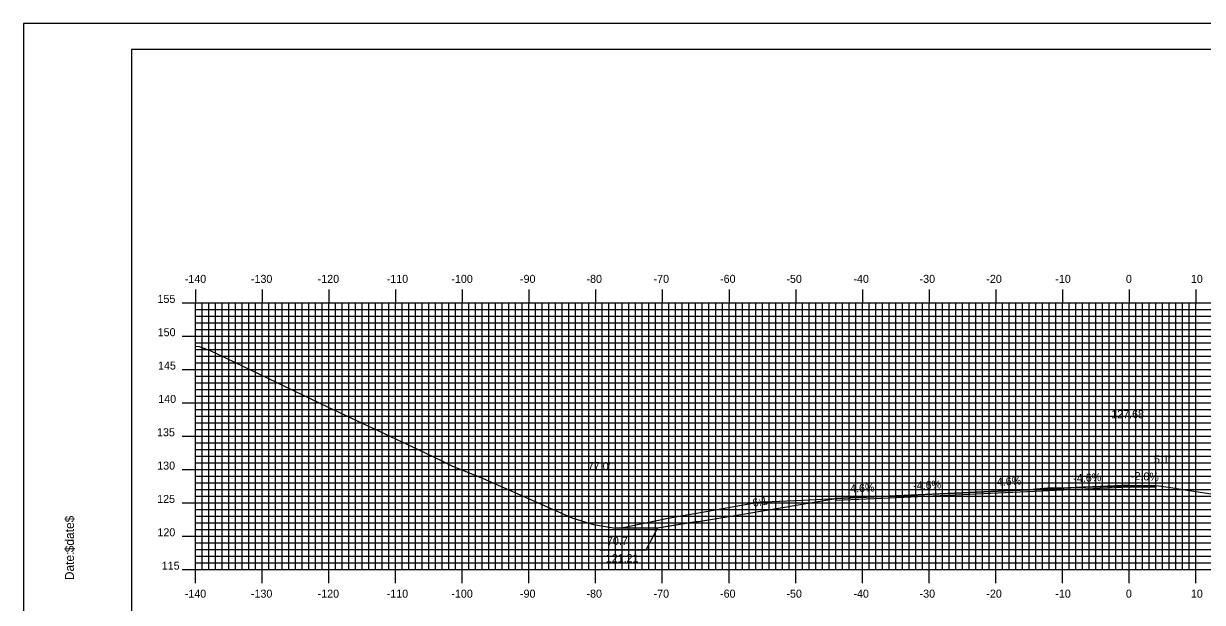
# Model space of a CAD drawing. Extents: x 851926 to 852269, y 366605 to 366825.
# Drawn here: x 851926.2 to 852103, y 366738.1 to 366824.9 of the extents above; entities that cross this region are included whole.
import ezdxf

# ---------------------------------------------------------------- set-up
doc = ezdxf.new("R2010")
doc.units = 0
for name, color, linetype in [('ANNOTATION', 7, 'Continuous'), ('BORDER', 7, 'Continuous'), ('D_Roadway_Centerline', 7, 'Continuous'), ('D_Roadway_Centerline_Text', 7, 'Continuous'), ('D_Roadway_Edge_Shoulder', 7, 'Continuous'), ('D_Roadway_Edge_TW', 7, 'Continuous'), ('D_Roadway_SlopeLines', 7, 'Continuous'), ('D_Text_Standard', 7, 'Continuous'), ('H_V ANNOTATION', 7, 'Continuous'), ('M_Roadway_Centerline', 7, 'Continuous'), ('MAJOR', 7, 'Continuous'), ('MINOR', 7, 'Continuous'), ('PLOT BOUNDARY', 7, 'Continuous'), ('S_Roadway_Centerline', 7, 'Continuous')]:
    doc.layers.add(name, color=color, linetype=linetype)

msp = doc.modelspace()

# ---------------------------------------------------------------- linework, layer by layer
at = {"layer": 'ANNOTATION'}
for points in [[(852027.25, 366750.26), (852021.25, 366749.26), (852014.95, 366749.3)], [(852012.59, 366746.05), (852019.52, 366746.05), (852021.25, 366749.26)]]:
    msp.add_lwpolyline(points, dxfattribs=at)
at = {"layer": 'BORDER'}
msp.add_lwpolyline([(851942.36, 366611.06), (852262.36, 366611.06), (852262.36, 366821.06), (851942.36, 366821.06)], close=True, dxfattribs=at)
at = {"layer": 'D_Roadway_Centerline'}
for p, q in [((852091.96, 366755.74), (852095.96, 366755.66)), ((852091.96, 366755.49), (852095.96, 366755.41))]:
    msp.add_line(p, q, dxfattribs=at)
for points in [[(852025.87, 366750.03), (852033.75, 366751.34), (852047.96, 366753.71), (852047.97, 366753.71), (852052.55, 366753.92), (852055.96, 366754.08), (852055.96, 366754.08), (852062.39, 366754.38), (852067.96, 366754.63), (852067.96, 366754.63), (852079.96, 366755.19), (852079.96, 366755.19), (852091.96, 366755.74), (852091.96, 366755.74), (852095.96, 366755.66)], [(852025.87, 366750.03), (852021.25, 366749.26), (852014.95, 366749.3)]]:
    msp.add_lwpolyline(points, dxfattribs=at)
at = {"layer": 'D_Roadway_Edge_Shoulder'}
for points in [[(852091.96, 366755.74), (852095.96, 366755.66), (852095.96, 366755.41), (852091.96, 366755.49)], [(852055.96, 366754.08), (852047.96, 366753.71), (852047.96, 366753.46), (852055.96, 366753.83)]]:
    msp.add_lwpolyline(points, close=True, dxfattribs=at)
at = {"layer": 'D_Roadway_Edge_TW'}
for points in [[(852079.96, 366755.19), (852067.96, 366754.63), (852067.96, 366754.38), (852079.96, 366754.94)], [(852091.96, 366755.74), (852079.96, 366755.19), (852079.96, 366754.94), (852091.96, 366755.49)], [(852067.96, 366754.63), (852055.96, 366754.08), (852055.96, 366753.83), (852067.96, 366754.38)]]:
    msp.add_lwpolyline(points, close=True, dxfattribs=at)
msp.add_lwpolyline([(852067.96, 366754.38), (852067.96, 366754.63)], dxfattribs=at)
at = {"layer": 'D_Roadway_SlopeLines'}
msp.add_line((852095.96, 366755.66), (852097.11, 366755.51), dxfattribs=at)
at = {"layer": 'MAJOR'}
for p, q in [((851951.96, 366785.06), (851951.96, 366783.06)), ((851961.96, 366785.06), (851961.96, 366783.06)), ((851971.96, 366785.06), (851971.96, 366783.06)), ((851981.96, 366785.06), (851981.96, 366783.06)), ((851991.96, 366785.06), (851991.96, 366783.06)), ((852001.96, 366785.06), (852001.96, 366783.06)), ((852011.96, 366785.06), (852011.96, 366783.06)), ((852021.96, 366785.06), (852021.96, 366783.06)), ((852031.96, 366785.06), (852031.96, 366783.06)), ((852041.96, 366785.06), (852041.96, 366783.06)), ((852051.96, 366785.06), (852051.96, 366783.06)), ((852061.96, 366785.06), (852061.96, 366783.06)), ((852071.96, 366785.06), (852071.96, 366783.06)), ((852081.96, 366785.06), (852081.96, 366783.06)), ((852091.96, 366785.06), (852091.96, 366783.06)), ((852101.96, 366785.06), (852101.96, 366783.06)), ((851949.96, 366783.06), (851951.96, 366783.06)), ((851951.96, 366783.06), (852231.96, 366783.06)), ((851951.96, 366743.06), (851951.96, 366783.06)), ((851951.96, 366743.06), (851951.96, 366783.06)), ((851951.96, 366783.06), (852231.96, 366783.06)), ((851961.96, 366743.06), (851961.96, 366783.06)), ((851971.96, 366743.06), (851971.96, 366783.06)), ((851981.96, 366743.06), (851981.96, 366783.06)), ((851991.96, 366743.06), (851991.96, 366783.06)), ((852001.96, 366743.06), (852001.96, 366783.06)), ((852011.96, 366743.06), (852011.96, 366783.06)), ((852021.96, 366743.06), (852021.96, 366783.06)), ((852031.96, 366743.06), (852031.96, 366783.06)), ((852041.96, 366743.06), (852041.96, 366783.06)), ((852051.96, 366743.06), (852051.96, 366783.06)), ((852061.96, 366743.06), (852061.96, 366783.06)), ((852071.96, 366743.06), (852071.96, 366783.06)), ((852081.96, 366743.06), (852081.96, 366783.06)), ((852091.96, 366743.06), (852091.96, 366783.06)), ((852101.96, 366743.06), (852101.96, 366783.06)), ((851949.96, 366778.06), (851951.96, 366778.06)), ((851951.96, 366778.06), (852231.96, 366778.06)), ((851949.96, 366773.06), (851951.96, 366773.06)), ((851951.96, 366773.06), (852231.96, 366773.06)), ((851949.96, 366768.06), (851951.96, 366768.06)), ((851951.96, 366768.06), (852231.96, 366768.06)), ((851949.96, 366763.06), (851951.96, 366763.06)), ((851951.96, 366763.06), (852231.96, 366763.06)), ((851949.96, 366758.06), (851951.96, 366758.06)), ((851951.96, 366758.06), (852231.96, 366758.06)), ((851949.96, 366753.06), (851951.96, 366753.06)), ((851951.96, 366753.06), (852231.96, 366753.06)), ((851949.96, 366748.06), (851951.96, 366748.06)), ((851951.96, 366748.06), (852231.96, 366748.06)), ((851949.96, 366743.06), (851951.96, 366743.06)), ((851951.96, 366743.06), (852231.96, 366743.06)), ((851951.96, 366743.06), (852231.96, 366743.06)), ((851951.96, 366741.05), (851951.96, 366743.06)), ((851961.96, 366741.05), (851961.96, 366743.06)), ((851971.96, 366741.05), (851971.96, 366743.06)), ((851981.96, 366741.05), (851981.96, 366743.06)), ((851991.96, 366741.05), (851991.96, 366743.06)), ((852001.96, 366741.05), (852001.96, 366743.06)), ((852011.96, 366741.05), (852011.96, 366743.06)), ((852021.96, 366741.05), (852021.96, 366743.06)), ((852031.96, 366741.05), (852031.96, 366743.06)), ((852041.96, 366741.05), (852041.96, 366743.06)), ((852051.96, 366741.05), (852051.96, 366743.06)), ((852061.96, 366741.05), (852061.96, 366743.06)), ((852071.96, 366741.05), (852071.96, 366743.06)), ((852081.96, 366741.05), (852081.96, 366743.06)), ((852091.96, 366741.05), (852091.96, 366743.06)), ((852101.96, 366741.05), (852101.96, 366743.06))]:
    msp.add_line(p, q, dxfattribs=at)
at = {"layer": 'MINOR'}
for p, q in [((851951.96, 366782.06), (852231.96, 366782.06)), ((851951.96, 366782.06), (851953.97, 366782.06)), ((851952.96, 366743.06), (851952.96, 366783.06)), ((851953.96, 366743.06), (851953.96, 366783.06)), ((851954.96, 366743.06), (851954.96, 366783.06)), ((851955.96, 366743.06), (851955.96, 366783.06)), ((851956.96, 366743.06), (851956.96, 366783.06)), ((851957.96, 366743.06), (851957.96, 366783.06)), ((851958.96, 366743.06), (851958.96, 366783.06)), ((851959.96, 366743.06), (851959.96, 366783.06)), ((851960.96, 366743.06), (851960.96, 366783.06)), ((851962.96, 366743.06), (851962.96, 366783.06)), ((851963.96, 366743.06), (851963.96, 366783.06)), ((851964.96, 366743.06), (851964.96, 366783.06)), ((851965.96, 366743.06), (851965.96, 366783.06)), ((851966.96, 366743.06), (851966.96, 366783.06)), ((851967.96, 366743.06), (851967.96, 366783.06)), ((851968.96, 366743.06), (851968.96, 366783.06)), ((851969.96, 366743.06), (851969.96, 366783.06)), ((851970.96, 366743.06), (851970.96, 366783.06)), ((851972.96, 366743.06), (851972.96, 366783.06)), ((851973.96, 366743.06), (851973.96, 366783.06)), ((851974.96, 366743.06), (851974.96, 366783.06)), ((851975.96, 366743.06), (851975.96, 366783.06)), ((851976.96, 366743.06), (851976.96, 366783.06)), ((851977.96, 366743.06), (851977.96, 366783.06)), ((851978.96, 366743.06), (851978.96, 366783.06)), ((851979.96, 366743.06), (851979.96, 366783.06)), ((851980.96, 366743.06), (851980.96, 366783.06)), ((851982.96, 366743.06), (851982.96, 366783.06)), ((851983.96, 366743.06), (851983.96, 366783.06)), ((851984.96, 366743.06), (851984.96, 366783.06)), ((851985.96, 366743.06), (851985.96, 366783.06)), ((851986.96, 366743.06), (851986.96, 366783.06)), ((851987.96, 366743.06), (851987.96, 366783.06)), ((851988.96, 366743.06), (851988.96, 366783.06)), ((851989.96, 366743.06), (851989.96, 366783.06)), ((851990.96, 366743.06), (851990.96, 366783.06)), ((851992.96, 366743.06), (851992.96, 366783.06)), ((851993.96, 366743.06), (851993.96, 366783.06)), ((851994.96, 366743.06), (851994.96, 366783.06)), ((851995.96, 366743.06), (851995.96, 366783.06)), ((851996.96, 366743.06), (851996.96, 366783.06)), ((851997.96, 366743.06), (851997.96, 366783.06)), ((851998.96, 366743.06), (851998.96, 366783.06)), ((851999.96, 366743.06), (851999.96, 366783.06)), ((852000.96, 366743.06), (852000.96, 366783.06)), ((852002.96, 366743.06), (852002.96, 366783.06)), ((852003.96, 366743.06), (852003.96, 366783.06)), ((852004.96, 366743.06), (852004.96, 366783.06)), ((852005.96, 366743.06), (852005.96, 366783.06)), ((852006.96, 366743.06), (852006.96, 366783.06)), ((852007.96, 366743.06), (852007.96, 366783.06)), ((852008.96, 366743.06), (852008.96, 366783.06)), ((852009.96, 366743.06), (852009.96, 366783.06)), ((852010.96, 366743.06), (852010.96, 366783.06)), ((852012.96, 366743.06), (852012.96, 366783.06)), ((852013.96, 366743.06), (852013.96, 366783.06)), ((852014.96, 366743.06), (852014.96, 366783.06)), ((852015.96, 366743.06), (852015.96, 366783.06)), ((852016.96, 366743.06), (852016.96, 366783.06)), ((852017.96, 366743.06), (852017.96, 366783.06)), ((852018.96, 366743.06), (852018.96, 366783.06)), ((852019.96, 366743.06), (852019.96, 366783.06)), ((852020.96, 366743.06), (852020.96, 366783.06)), ((852022.96, 366743.06), (852022.96, 366783.06)), ((852023.96, 366743.06), (852023.96, 366783.06)), ((852024.96, 366743.06), (852024.96, 366783.06)), ((852025.96, 366743.06), (852025.96, 366783.06)), ((852026.96, 366743.06), (852026.96, 366783.06)), ((852027.96, 366743.06), (852027.96, 366783.06)), ((852028.96, 366743.06), (852028.96, 366783.06)), ((852029.96, 366743.06), (852029.96, 366783.06)), ((852030.96, 366743.06), (852030.96, 366783.06)), ((852032.96, 366743.06), (852032.96, 366783.06)), ((852033.96, 366743.06), (852033.96, 366783.06)), ((852034.96, 366743.06), (852034.96, 366783.06)), ((852035.96, 366743.06), (852035.96, 366783.06)), ((852036.96, 366743.06), (852036.96, 366783.06)), ((852037.96, 366743.06), (852037.96, 366783.06)), ((852038.96, 366743.06), (852038.96, 366783.06)), ((852039.96, 366743.06), (852039.96, 366783.06)), ((852040.96, 366743.06), (852040.96, 366783.06)), ((852042.96, 366743.06), (852042.96, 366783.06)), ((852043.96, 366743.06), (852043.96, 366783.06)), ((852044.96, 366743.06), (852044.96, 366783.06)), ((852045.96, 366743.06), (852045.96, 366783.06)), ((852046.96, 366743.06), (852046.96, 366783.06)), ((852047.96, 366743.06), (852047.96, 366783.06)), ((852048.96, 366743.06), (852048.96, 366783.06)), ((852049.96, 366743.06), (852049.96, 366783.06)), ((852050.96, 366743.06), (852050.96, 366783.06)), ((852052.96, 366743.06), (852052.96, 366783.06)), ((852053.96, 366743.06), (852053.96, 366783.06)), ((852054.96, 366743.06), (852054.96, 366783.06)), ((852055.96, 366743.06), (852055.96, 366783.06)), ((852056.96, 366743.06), (852056.96, 366783.06)), ((852057.96, 366743.06), (852057.96, 366783.06)), ((852058.96, 366743.06), (852058.96, 366783.06)), ((852059.96, 366743.06), (852059.96, 366783.06)), ((852060.96, 366743.06), (852060.96, 366783.06)), ((852062.96, 366743.06), (852062.96, 366783.06)), ((852063.96, 366743.06), (852063.96, 366783.06)), ((852064.96, 366743.06), (852064.96, 366783.06)), ((852065.96, 366743.06), (852065.96, 366783.06)), ((852066.96, 366743.06), (852066.96, 366783.06)), ((852067.96, 366743.06), (852067.96, 366783.06)), ((852068.96, 366743.06), (852068.96, 366783.06)), ((852069.96, 366743.06), (852069.96, 366783.06)), ((852070.96, 366743.06), (852070.96, 366783.06)), ((852072.96, 366743.06), (852072.96, 366783.06)), ((852073.96, 366743.06), (852073.96, 366783.06)), ((852074.96, 366743.06), (852074.96, 366783.06)), ((852075.96, 366743.06), (852075.96, 366783.06)), ((852076.96, 366743.06), (852076.96, 366783.06)), ((852077.96, 366743.06), (852077.96, 366783.06)), ((852078.96, 366743.06), (852078.96, 366783.06)), ((852079.96, 366743.06), (852079.96, 366783.06)), ((852080.96, 366743.06), (852080.96, 366783.06)), ((852082.96, 366743.06), (852082.96, 366783.06)), ((852083.96, 366743.06), (852083.96, 366783.06)), ((852084.96, 366743.06), (852084.96, 366783.06)), ((852085.96, 366743.06), (852085.96, 366783.06)), ((852086.96, 366743.06), (852086.96, 366783.06)), ((852087.96, 366743.06), (852087.96, 366783.06)), ((852088.96, 366743.06), (852088.96, 366783.06)), ((852089.96, 366743.06), (852089.96, 366783.06)), ((852090.96, 366743.06), (852090.96, 366783.06)), ((852092.96, 366743.06), (852092.96, 366783.06)), ((852093.96, 366743.06), (852093.96, 366783.06)), ((852094.96, 366743.06), (852094.96, 366783.06)), ((852095.96, 366743.06), (852095.96, 366783.06)), ((852096.96, 366743.06), (852096.96, 366783.06)), ((852097.96, 366743.06), (852097.96, 366783.06)), ((852098.96, 366743.06), (852098.96, 366783.06)), ((852099.96, 366743.06), (852099.96, 366783.06)), ((852100.96, 366743.06), (852100.96, 366783.06)), ((851951.96, 366781.06), (852231.96, 366781.06)), ((851951.96, 366781.06), (851953.97, 366781.06)), ((851951.96, 366780.06), (852231.96, 366780.06)), ((851951.96, 366780.06), (851953.97, 366780.06)), ((851951.96, 366779.06), (852231.96, 366779.06)), ((851951.96, 366779.06), (851953.97, 366779.06)), ((851951.96, 366777.06), (852231.96, 366777.06)), ((851951.96, 366777.06), (851953.97, 366777.06)), ((851951.96, 366776.06), (852231.96, 366776.06)), ((851951.96, 366776.06), (851953.97, 366776.06)), ((851951.96, 366775.06), (852231.96, 366775.06)), ((851951.96, 366775.06), (851953.97, 366775.06)), ((851951.96, 366774.06), (852231.96, 366774.06)), ((851951.96, 366774.06), (851953.97, 366774.06)), ((851951.96, 366772.06), (852231.96, 366772.06)), ((851951.96, 366772.06), (851953.97, 366772.06)), ((851951.96, 366771.06), (852231.96, 366771.06)), ((851951.96, 366771.06), (851953.97, 366771.06)), ((851951.96, 366770.06), (852231.96, 366770.06)), ((851951.96, 366770.06), (851953.97, 366770.06)), ((851951.96, 366769.06), (852231.96, 366769.06)), ((851951.96, 366769.06), (851953.97, 366769.06)), ((851951.96, 366767.06), (852231.96, 366767.06)), ((851951.96, 366767.06), (851953.97, 366767.06)), ((851951.96, 366766.06), (852231.96, 366766.06)), ((851951.96, 366766.06), (851953.97, 366766.06)), ((851951.96, 366765.06), (852231.96, 366765.06)), ((851951.96, 366765.06), (851953.97, 366765.06)), ((851951.96, 366764.06), (852231.96, 366764.06)), ((851951.96, 366764.06), (851953.97, 366764.06)), ((851951.96, 366762.06), (852231.96, 366762.06)), ((851951.96, 366762.06), (851953.97, 366762.06)), ((851951.96, 366761.06), (852231.96, 366761.06)), ((851951.96, 366761.06), (851953.97, 366761.06)), ((851951.96, 366760.06), (852231.96, 366760.06)), ((851951.96, 366760.06), (851953.97, 366760.06)), ((851951.96, 366759.06), (852231.96, 366759.06)), ((851951.96, 366759.06), (851953.97, 366759.06)), ((851951.96, 366757.06), (852231.96, 366757.06)), ((851951.96, 366757.06), (851953.97, 366757.06)), ((851951.96, 366756.06), (852231.96, 366756.06)), ((851951.96, 366756.06), (851953.97, 366756.06)), ((851951.96, 366755.06), (852231.96, 366755.06)), ((851951.96, 366755.06), (851953.97, 366755.06)), ((851951.96, 366754.06), (852231.96, 366754.06)), ((851951.96, 366754.06), (851953.97, 366754.06)), ((851951.96, 366752.06), (852231.96, 366752.06)), ((851951.96, 366752.06), (851953.97, 366752.06)), ((851951.96, 366751.06), (852231.96, 366751.06)), ((851951.96, 366751.06), (851953.97, 366751.06)), ((851951.96, 366750.06), (852231.96, 366750.06)), ((851951.96, 366750.06), (851953.97, 366750.06)), ((851951.96, 366749.06), (852231.96, 366749.06)), ((851951.96, 366749.06), (851953.97, 366749.06)), ((851951.96, 366747.06), (852231.96, 366747.06)), ((851951.96, 366747.06), (851953.97, 366747.06)), ((851951.96, 366746.06), (852231.96, 366746.06)), ((851951.96, 366746.06), (851953.97, 366746.06)), ((851951.96, 366745.06), (852231.96, 366745.06)), ((851951.96, 366745.06), (851953.97, 366745.06)), ((851951.96, 366744.06), (852231.96, 366744.06)), ((851951.96, 366744.06), (851953.97, 366744.06))]:
    msp.add_line(p, q, dxfattribs=at)
at = {"layer": 'PLOT BOUNDARY'}
msp.add_lwpolyline([(851926.18, 366604.94), (852266.18, 366604.94), (852266.18, 366824.94), (851926.18, 366824.94)], close=True, dxfattribs=at)
at = {"layer": 'S_Roadway_Centerline'}
msp.add_lwpolyline([(851951.96, 366776.56), (851952.53, 366776.51), (851954.16, 366775.94), (851958.96, 366773.64), (851971.84, 366767.44), (851985.43, 366761.04), (851988.91, 366759.38), (851990.41, 366758.64), (851995.11, 366756.72), (852008.53, 366750.78), (852011.64, 366749.83), (852014.95, 366749.3), (852016.08, 366749.39), (852022.61, 366750.71), (852024.75, 366751.15), (852028.23, 366751.71), (852036.62, 366753.21), (852037.28, 366753.22), (852044.09, 366753.53), (852047.84, 366753.75), (852051.91, 366754.05), (852052.84, 366754.03), (852053.97, 366754.03), (852060.57, 366754.34), (852062.57, 366754.42), (852073.02, 366754.86), (852076.21, 366755.03), (852077, 366755.09), (852079.71, 366755.33), (852082.77, 366755.39), (852085.14, 366755.48), (852087.77, 366755.48), (852094.33, 366755.69), (852096.01, 366755.66), (852098.2, 366755.37), (852099.72, 366755.15), (852110.7, 366753.41)], dxfattribs=at)

# ---------------------------------------------------------------- texts
at = {"layer": 'ANNOTATION'}
for s, rotation, p in [('-4.6%', 2.6337, (852071.6, 366755.6)), ('-4.6%', 2.6337, (852083.61, 366756.15)), ('-2.0%', 357.7094, (852092.21, 366756.53)), ('-4.6%', 2.6339, (852049.61, 366754.59)), ('-4.6%', 2.6338, (852059.6, 366755.05)), ('6:1', 9.4616, (852035.59, 366752.48)), ("70.7' ", 360, (852013.66, 366746.78)), ('121.21', 360, (852013.48, 366744.18))]:
    msp.add_text(s, height=1.2, rotation=rotation, dxfattribs=at).set_placement(p)
at = {"layer": 'BORDER'}
for s, p in [('$date$', (851933.73, 366745.67)), ('Date:', (851933.73, 366741.49))]:
    msp.add_text(s, height=1.339, rotation=90, dxfattribs=at).set_placement(p)
at = {"layer": 'D_Roadway_Centerline_Text'}
msp.add_text('127.68', height=1.2, dxfattribs=at).set_placement((852089.28, 366765.77))
at = {"layer": 'D_Text_Standard'}
for s, p in [("5.1'", (852095.69, 366759.01)), ("77.0'", (852010.79, 366757.98))]:
    msp.add_text(s, height=1.2, dxfattribs=at).set_placement(p)
at = {"layer": 'H_V ANNOTATION'}
for s, p in [('-140', (851950.35, 366786.06)), ('-130', (851960.27, 366786.06)), ('-120', (851970.28, 366786.06)), ('-110', (851980.63, 366786.06)), ('-100', (851990.33, 366786.06)), ('-90', (852000.62, 366786.06)), ('-80', (852010.59, 366786.06)), ('-70', (852020.65, 366786.06)), ('-60', (852030.62, 366786.06)), ('-50', (852040.57, 366786.06)), ('-40', (852050.62, 366786.06)), ('-30', (852060.54, 366786.06)), ('-20', (852070.55, 366786.06)), ('-10', (852080.89, 366786.06)), ('0', (852091.48, 366786.06)), ('10', (852101.22, 366786.06)), ('155', (851946.26, 366783.06)), ('150', (851946.29, 366778.06)), ('145', (851946.34, 366773.06)), ('140', (851946.37, 366768.06)), ('135', (851946.19, 366763.06)), ('130', (851946.22, 366758.06)), ('125', (851946.21, 366753.06)), ('120', (851946.25, 366748.06)), ('115', (851946.9, 366743.06)), ('-140', (851950.35, 366738.86)), ('-130', (851960.27, 366738.86)), ('-120', (851970.28, 366738.86)), ('-110', (851980.63, 366738.86)), ('-100', (851990.33, 366738.86)), ('-90', (852000.62, 366738.86)), ('-80', (852010.59, 366738.86)), ('-70', (852020.65, 366738.86)), ('-60', (852030.62, 366738.86)), ('-50', (852040.57, 366738.86)), ('-40', (852050.62, 366738.86)), ('-30', (852060.54, 366738.86)), ('-20', (852070.55, 366738.86)), ('-10', (852080.89, 366738.86)), ('0', (852091.48, 366738.86)), ('10', (852101.22, 366738.86))]:
    msp.add_text(s, height=1.2, dxfattribs=at).set_placement(p)
at = {"layer": 'M_Roadway_Centerline'}
for s, p in [('C', (852079.71, 366755.33)), ('L', (852079.71, 366755.32)), ('C', (852051.9, 366754.05)), ('L', (852051.91, 366754.04))]:
    msp.add_text(s, height=0.0146, dxfattribs=at).set_placement(p)
at = {"layer": 'MAJOR'}
msp.add_text('-', height=0.012, dxfattribs=at).set_placement((851951.96, 366743.06))

doc.saveas('drawing.dxf')
